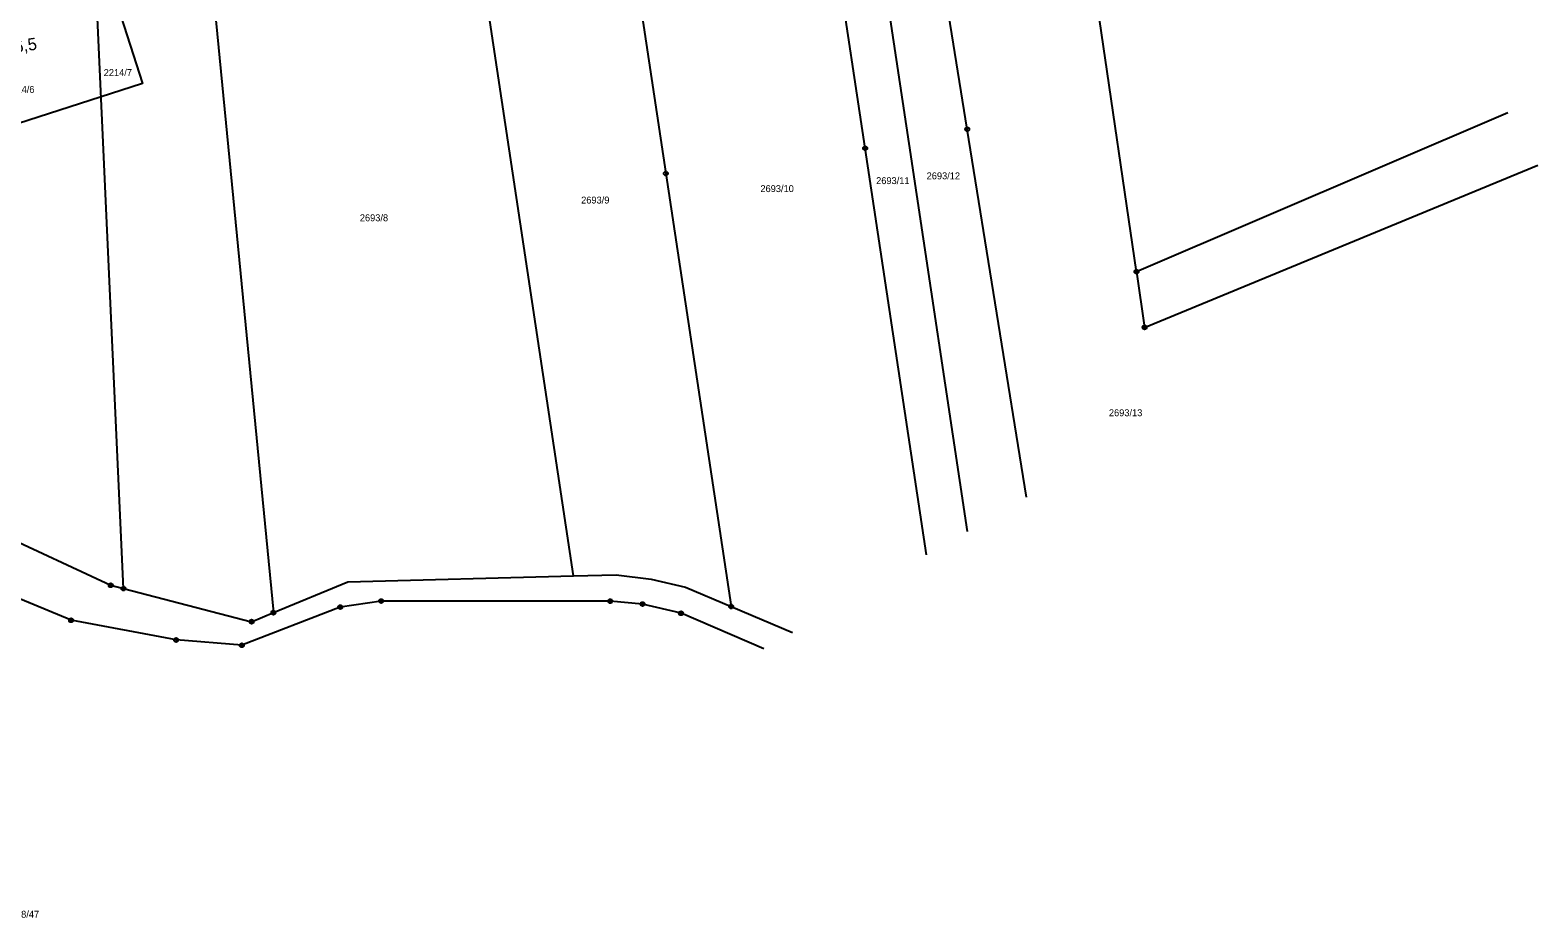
# Model space of a CAD drawing. Extents: x -758836 to -757729, y -1175316 to -1174366.
# Drawn here: x -758099.9 to -757729.1, y -1175005.1 to -1174786.9 of the extents above; entities that cross this region are included whole.
import ezdxf

# ---------------------------------------------------------------- set-up
doc = ezdxf.new("R2010")
doc.units = 0
for name, color, linetype in [('_NOR-pomocná', 7, 'Continuous'), ('_NOR-popis', 7, 'Continuous'), ('Hranice parcel', 7, 'Continuous'), ('Parcelní čísla', 7, 'Continuous'), ('Značky bodu BP', 7, 'Continuous')]:
    doc.layers.add(name, color=color, linetype=linetype)

msp = doc.modelspace()

# ---------------------------------------------------------------- linework, layer by layer
at = {"layer": '_NOR-pomocná'}
msp.add_lwpolyline([(-758217.71, -1174690.84), (-758117.77, -1174658.65), (-758072.24, -1174800), (-758172.18, -1174832.19)], close=True, dxfattribs=at)
at = {"layer": 'Hranice parcel'}
for p, q in [((-757966.21, -1174921.06), (-757991.64, -1174752.6)), ((-758056.09, -1174765.35), (-758040.03, -1174930.09)), ((-758076.9, -1174924.17), (-758083.84, -1174772.54)), ((-757827.8, -1174846.29), (-757836.93, -1174784.23)), ((-757927.46, -1174928.58), (-757912.42, -1174934.95))]:
    msp.add_line(p, q, dxfattribs=at)
for points in [[(-757854.84, -1174901.71), (-757869.41, -1174811.27), (-757893.96, -1174658.87)], [(-757905.12, -1174673.47), (-757883.79, -1174814.77), (-757869.4, -1174910.11)], [(-757879.43, -1174915.9), (-757894.52, -1174815.94), (-757914.95, -1174680.62)], [(-757959.61, -1174715.65), (-757943.53, -1174822.15), (-757927.46, -1174928.58)], [(-757736.5, -1174807.25), (-757827.8, -1174846.29)], [(-757827.8, -1174846.29), (-757825.79, -1174859.97), (-757729.1, -1174820.07)], [(-758114.13, -1174910.8), (-758107.54, -1174910.58), (-758080.03, -1174923.36), (-758076.9, -1174924.17)], [(-757919.47, -1174939.02), (-757939.8, -1174930.25), (-757949.26, -1174927.98), (-757957.21, -1174927.28), (-758013.54, -1174927.25), (-758023.59, -1174928.73), (-758047.8, -1174938.11), (-758063.96, -1174936.81), (-758089.79, -1174931.96), (-758110.46, -1174923.41), (-758137.06, -1174918.45)], [(-758040.03, -1174930.09), (-758021.7, -1174922.52), (-757966.21, -1174921.06)], [(-757966.21, -1174921.06), (-757955.71, -1174920.78), (-757947.16, -1174921.89), (-757938.71, -1174923.81), (-757927.46, -1174928.58)], [(-758076.9, -1174924.17), (-758045.39, -1174932.31), (-758040.03, -1174930.09)]]:
    msp.add_lwpolyline(points, dxfattribs=at)
at = {"layer": 'Značky bodu BP'}
for centre, radius in [((-757869.41, -1174811.27), 0.5), ((-757869.41, -1174811.27), 0.0303), ((-757894.52, -1174815.94), 0.5), ((-757894.52, -1174815.94), 0.0303), ((-757943.53, -1174822.15), 0.5), ((-757943.53, -1174822.15), 0.0303), ((-757827.8, -1174846.29), 0.5), ((-757827.8, -1174846.29), 0.0303), ((-757825.79, -1174859.97), 0.5), ((-757825.79, -1174859.97), 0.0303), ((-758080.03, -1174923.36), 0.5), ((-758080.03, -1174923.36), 0.0303), ((-758076.9, -1174924.17), 0.5), ((-758076.9, -1174924.17), 0.0303), ((-758023.59, -1174928.73), 0.5), ((-758023.59, -1174928.73), 0.0303), ((-758013.54, -1174927.25), 0.5), ((-758013.54, -1174927.25), 0.0303), ((-757957.21, -1174927.28), 0.5), ((-757957.21, -1174927.28), 0.0303), ((-757949.26, -1174927.98), 0.5), ((-757949.26, -1174927.98), 0.0303), ((-757927.46, -1174928.58), 0.5), ((-757927.46, -1174928.58), 0.0303), ((-758089.79, -1174931.96), 0.5), ((-758089.79, -1174931.96), 0.0303), ((-758045.39, -1174932.31), 0.5), ((-758045.39, -1174932.31), 0.0303), ((-758040.03, -1174930.09), 0.5), ((-758040.03, -1174930.09), 0.0303), ((-757939.8, -1174930.25), 0.5), ((-757939.8, -1174930.25), 0.0303), ((-758063.96, -1174936.81), 0.5), ((-758063.96, -1174936.81), 0.0303), ((-758047.8, -1174938.11), 0.5), ((-758047.8, -1174938.11), 0.0303)]:
    msp.add_circle(centre, radius, dxfattribs=at)

# ---------------------------------------------------------------- texts
at = {"layer": '_NOR-popis'}
msp.add_text('106,5', height=3, rotation=8.6527, dxfattribs=at).set_placement((-758107.95, -1174793.19))
at = {"layer": 'Parcelní čísla'}
for s, p in [('2214/7', (-758081.77, -1174798.2)), ('2214/6', (-758105.74, -1174802.34)), ('2693/10', (-757920.28, -1174826.72)), ('2693/11', (-757891.82, -1174824.76)), ('2693/12', (-757879.4, -1174823.58)), ('2693/9', (-757964.36, -1174829.53)), ('2693/8', (-758018.78, -1174833.89)), ('2693/13', (-757834.58, -1174881.81)), ('2678/47', (-758105.86, -1175005.08))]:
    msp.add_text(s, height=1.7, dxfattribs=at).set_placement(p)

doc.saveas('drawing.dxf')
